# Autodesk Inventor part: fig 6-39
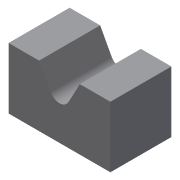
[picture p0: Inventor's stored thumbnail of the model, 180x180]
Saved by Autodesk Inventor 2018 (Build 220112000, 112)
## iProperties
Created: 2005-12
Part Number: fig 6-39
Document SubType Name: Modeling
Designer: CADCIM
Density: 1 g/cm^3
Material: Generic
Appearance: Default
Author: CADCIM
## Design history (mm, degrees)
sketch "Sketch1"
  geometry: L1 (10, 15)-(25, 15); L2 (25, 15)-(25, -15); L3 (25, -15)-(-25, -15); L4 (-25, -15)-(-25, 15); L5 (-25, 15)-(-10, 15); L6 (-10, 15)-(-2, 0); L7 (-2, 0)-(2, 0); L8 (2, 0)-(10, 15); 1 further point
  constraints: 16 end point, 3 equal length, 3 parallel, 1 collinear, 1 horizontal, 1 perpendicular, 1 other
  dimensions: "d0" = 50 distance of L2.end L3.end; "d1" = 25 distance from line of point (0, 0) L2; "d2" = 30 distance of L1.end L2.end; "d3" = 15 distance of L1.start L1.end; "d4" = 15 distance between parallel lines of L1 L7; "d5" = 4 distance of L6.end L7.end; "d6" = 15 distance from line of point (0, 0) L3
extrude "Extrusion1" new body sketch "Sketch1" stored distance "d7" = 30; taper "d8" = 0 deg
fillet "Fillet4" dims "d11" = 5
body "Solid1"
